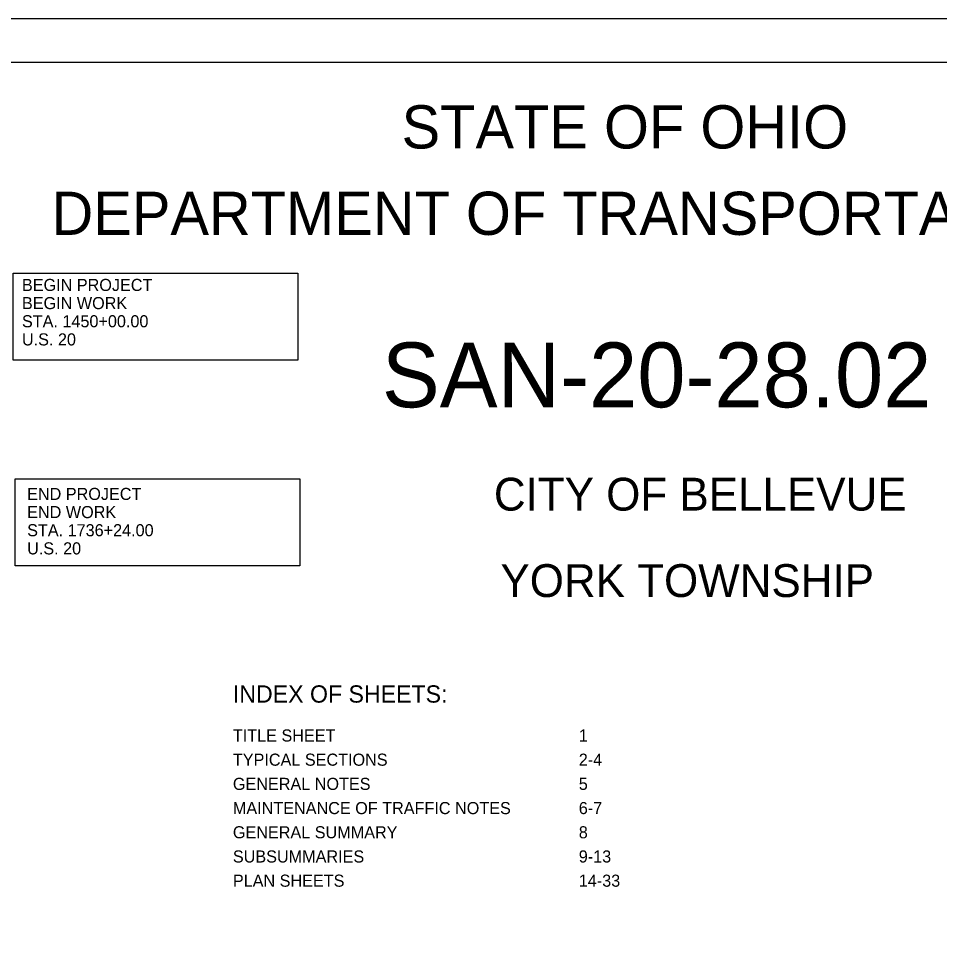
# Model space of a CAD drawing. Extents: x 0 to 34, y 0 to 22.
# Drawn here: x 9.37 to 20.01, y 11.1 to 22 of the extents above; entities that cross this region are included whole.
import ezdxf

# ---------------------------------------------------------------- set-up
doc = ezdxf.new("R2010")
doc.units = 0
for name, color, linetype in [('SH_Border', 7, 'Continuous'), ('SH_Cut_Line', 7, 'Continuous'), ('SH_Text', 7, 'Continuous')]:
    doc.layers.add(name, color=color, linetype=linetype)

msp = doc.modelspace()

# ---------------------------------------------------------------- linework, layer by layer
at = {"layer": 'SH_Border'}
msp.add_lwpolyline([(1.5, 21.5), (33.5, 21.5), (33.5, 0.5), (1.5, 0.5)], close=True, dxfattribs=at)
at = {"layer": 'SH_Cut_Line'}
msp.add_lwpolyline([(0, 0), (34, 0), (34, 22), (0, 22)], close=True, dxfattribs=at)
at = {"layer": 'SH_Text'}
for points in [[(9.305, 19.057), (12.596, 19.057), (12.596, 18.052), (9.305, 18.052)], [(9.325, 16.677), (12.617, 16.677), (12.617, 15.671), (9.325, 15.671)]]:
    msp.add_lwpolyline(points, close=True, dxfattribs=at)

# ---------------------------------------------------------------- texts
for s, height, p in [('STATE OF OHIO', 0.5, (13.795, 20.5)), ('DEPARTMENT OF TRANSPORTATION', 0.5, (9.747, 19.5)), ('BEGIN PROJECT', 0.14, (9.405, 18.851)), ('BEGIN WORK', 0.14, (9.405, 18.641)), ('STA. 1450+00.00', 0.14, (9.405, 18.431)), ('U.S. 20', 0.14, (9.405, 18.221)), ('SAN-20-28.02', 0.75, (13.567, 17.505)), (' CITY OF BELLEVUE', 0.38, (14.721, 16.31)), ('END PROJECT', 0.14, (9.465, 16.433)), ('END WORK', 0.14, (9.465, 16.223)), ('STA. 1736+24.00', 0.14, (9.465, 16.013)), ('U.S. 20', 0.14, (9.465, 15.803)), ('YORK TOWNSHIP', 0.38, (14.938, 15.31)), ('INDEX OF SHEETS:', 0.2, (11.844, 14.088)), ('TITLE SHEET', 0.14, (11.844, 13.638)), ('1', 0.14, (15.844, 13.638)), ('TYPICAL SECTIONS', 0.14, (11.844, 13.358)), ('2-4', 0.14, (15.844, 13.358)), ('GENERAL NOTES', 0.14, (11.844, 13.078)), ('5', 0.14, (15.844, 13.078)), ('MAINTENANCE OF TRAFFIC NOTES', 0.14, (11.844, 12.798)), ('6-7', 0.14, (15.844, 12.798)), ('GENERAL SUMMARY', 0.14, (11.844, 12.518)), ('8', 0.14, (15.844, 12.518)), ('SUBSUMMARIES', 0.14, (11.844, 12.238)), ('9-13', 0.14, (15.844, 12.238)), ('PLAN SHEETS', 0.14, (11.844, 11.958)), ('14-33', 0.14, (15.844, 11.958))]:
    msp.add_text(s, height=height, dxfattribs=at).set_placement(p)

doc.saveas('drawing.dxf')
